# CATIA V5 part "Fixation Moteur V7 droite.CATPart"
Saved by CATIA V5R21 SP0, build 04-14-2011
Part number: MOTEURDROIT
Bounding box of the stored display mesh (mm): x -4.2 to 4.2, y -40 to 0, z -20 to 40
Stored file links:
  C:\Users\2027.DESARCY-LEMIE30\Desktop\V16(05.04.2023)\Fixation Moteur V7 droite.CATPart
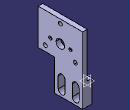
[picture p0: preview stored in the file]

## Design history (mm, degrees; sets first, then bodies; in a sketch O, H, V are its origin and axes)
Body1 (main body)
  Sketch1 on yz-plane, origin (0, 0, 0), H (0, 1, 0), V (0, 0, 1)
    line L1 (-40, 40) -> (0, 40)
    line L2 (0, 40) -> (0, 0)
    line L3 (0, 0) -> (-40, 0)
    line L4 (-40, 0) -> (-40, 40)
    point P3 (0, 0)
    length L4 = 40
    length L1 = 40
    horizontal: L1 H, L3 H
    vertical: L2 V, L4 V
    coincidence: P3 O
  Pad1: profile Sketch1, direction (1, 0, 0), length 4.2
  Sketch2 on end face of Pad1, origin (4.2, 0, 0), H (0, 1, 0), V (0, 0, 1)
    line L1 (-25, 0) -> (0, 0)
    line L2 (0, 0) -> (0, -20)
    line L3 (0, -20) -> (-25, -20)
    line L4 (-25, -20) -> (-25, 0)
    point P2 (0, 0)
    length L2 = 20
    length L3 = 25
    horizontal: L1 H, L3 H
    vertical: L2 V, L4 V
    coincidence: P2 O
  Pad2: profile Sketch2, direction (-1, 0, 0), length 8.4
  Sketch3 on end face of Pad2, origin (-4.2, 0, 0), H (0, -1, 0), V (0, 0, 1)
    point P1 (3.15, -5)
    line L1 (9.35, -5) -> (9.35, -15)
    line L2 (3.15, -15) -> (3.15, -5)
    point P2 (9.35, -5)
    point P3 (9.35, -15)
    point P4 (3.15, -15)
    axis line L3 (12.5, 2.3624) -> (12.5, -21.6714)
    reference projected line E1 (25, 0) -> (25, -20) from edge [end face of Pad2 | face of Pad2 from Sketch2.L4]
    arc A1 centre (6.25, -5) radius 3.1 from (9.35, -5) to (3.15, -5) ccw
    point P8 (10.7649, -15.4491)
    arc A2 centre (6.25, -15) radius 3.1 from (3.15, -15) to (9.35, -15) ccw
    point P9 (6.25, -15)
    point P10 (3.15, -15)
    point P11 (9.35, -15)
    point P12 (21.85, -5)
    point P13 (21.85, -15)
    line L4 (21.85, -15) -> (21.85, -5)
    point P14 (15.65, -5)
    arc A3 centre (18.75, -5) radius 3.1 from (15.65, -5) to (21.85, -5) cw
    point P16 (15.65, -15)
    line L5 (15.65, -5) -> (15.65, -15)
    point P17 (15.65, -15)
    point P18 (21.85, -15)
    point P19 (18.75, -15)
    arc A4 centre (18.75, -15) radius 3.1 from (21.85, -15) to (15.65, -15) cw
    reference projected line E2 (25, -20) -> (0, -20) from edge [end face of Pad2 | face of Pad2 from Sketch2.L3]
    distance L3 E1 = 12.5
    radius A1 = 3.1
    distance P9 P19 = 12.5
    length L4 = 10
    distance A4 E2 = 1.9
    vertical: L1 V, L2 V, L3 V
    tangency: A1 L1, A1 L2, A2 L1, A2 L2
    coincidence: P4 A2, L1 P11, L2 P10, P3 P11, P4 P10, P13 P18, P16 P17
    symmetry: P1 P12 L3, P4 P13 L3, L2 L4 L3, P2 P14 L3, A1 A3 L3, P3 P16 L3, L1 L5 L3, P11 P17 L3, P10 P18 L3, A2 A4 L3
  Pocket1: profile Sketch3, direction (1, 0, 0), through (limit type 3)
  Sketch4 on start face of Pad1, origin (0, 0, 0), H (0, -1, 0), V (0, 0, 1)
    construction line L1 (0, 20.75) -> (40, 20.75)
    point P1 (0, 20.75)
    point P2 (40, 20.75)
    reference projected line E1 (0, 40) -> (40, 40) from edge [start face of Pad1 | face of Pad1 from Sketch1.L1]
    reference projected line E2 (0, 0) -> (0, 40) from edge [start face of Pad1 | face of Pad2]
    reference projected line E3 (40, 40) -> (40, 0) from edge [start face of Pad1 | face of Pad1 from Sketch1.L4]
    construction line L2 (20, 40) -> (20, 0)
    point P3 (20, 40)
    point P4 (20, 0)
    reference projected line E4 (0, 40) -> (40, 40) from edge [start face of Pad1 | face of Pad1 from Sketch1.L1]
    reference projected line E5 (40, 0) -> (0, 0) from edge [start face of Pad1 | face of Pad1 from Sketch1.L3]
    reference projected line E6 (40, 40) -> (40, 0) from edge [start face of Pad1 | face of Pad1 from Sketch1.L4]
    circle A1 centre (20, 20.75) radius 4
    point P5 (20, 20.75)
    construction line L3 (20, 20.75) -> (0, 9.203)
    point P6 (0, 9.203)
    axis line L4 (20, 20.75) -> (40, 9.203)
    point P7 (40, 9.203)
    reference projected line E7 (40, 40) -> (40, 0) from edge [start face of Pad1 | face of Pad1 from Sketch1.L4]
    circle A2 centre (20, 36.3385) radius 1.75
    point P8 (20, 36.3385)
    point P9 (33.5, 12.9558)
    circle A3 centre (33.5, 12.9558) radius 1.75
    point P10 (6.5, 12.9558)
    circle A4 centre (6.5, 12.9558) radius 1.75
    distance E1 L1 = 19.25
    distance L2 E6 = 20
    radius A1 = 4
    angle L3 L2 = 120
    angle L2 L4 = 120
    radius A2 = 1.75
    distance P9 P10 = 27
    coincidence: P1 E2, P2 E3, E4 P3, P4 E5, P6 V, P7 E7, P8 L2, P5 L1, P5 L2
    vertical: L2 V
    symmetry: A2 A3 L3, A3 A4 L2
  Pocket2: profile Sketch4, direction (1, 0, 0), through (limit type 3)
  Sketch5 on start face of Pad1, origin (0, 0, 0), H (0, -1, 0), V (0, 0, 1)
    point P1 (40, 0)
    line L1 (40, 0) -> (25, 0)
    line L2 (25, 0) -> (25, 8)
    line L3 (25, 8) -> (40, 8)
    line L4 (40, 8) -> (40, 0)
    reference projected line E1 (0, -20) -> (0, 0) from edge [end face of Pad2 | face of Pad2 from Sketch2.L2]
    reference projected line E2 (25, 0) -> (25, -20) from edge [end face of Pad2 | face of Pad2 from Sketch2.L4]
    reference projected point E3 (40, 0) from vertex [face of Pad1 from Sketch1.L3 | start face of Pad1 | face of Pad1 from Sketch1.L4]
    length L2 = 8
    length L3 = 15
    distance E1 E2 = 25 (reference)
    horizontal: L1 H, L3 H
    vertical: L2 V, L4 V
    coincidence: P1 E3
  Pocket3: profile Sketch5, direction (1, 0, 0), through (limit type 3)
  Sketch6 on start face of Pad1, origin (0, -33.8289, 21.1001), H (0, 1, 0), V (0, 0, -1)
    point P1 (22.8289, 0.3501)
    axis line L1 (13.8289, 0.3501) -> (40.6944, 0.3501)
    point P2 (13.8289, 0.3501)
    reference projected circle E1 centre (13.8289, 0.3501) radius 4 from edge [start face of Pad1 | face of Pocket2 from Sketch4.A1]
    reference projected circle E2 centre (13.8289, 0.3501) radius 4 from edge [start face of Pad1 | face of Pocket2 from Sketch4.A1]
    distance P1 E2 = 5
    horizontal: L1 H
    concentricity: P2 E1
    coincidence: P1 L1
  Hole1: placed by Sketch6, at (0, -11, 20.75) direction (1, 0, 0), diameter 3, through (limit type 6), counterbore diameter 6, counterbore depth 3
  RectPattern1: of Hole1, direction 1 instances 2, spacing 18, along face of Pad1 from Sketch1.L1 reversed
